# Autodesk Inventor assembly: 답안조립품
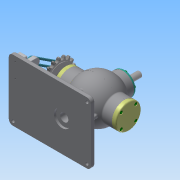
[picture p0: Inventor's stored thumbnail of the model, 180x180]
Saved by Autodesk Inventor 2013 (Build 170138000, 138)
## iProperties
Created: 2017-07
Part Number: 답안조립품
Document SubType Name: Assembly
Designer: Administrator
Author: Administrator
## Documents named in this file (20)
- C:\Users\Administrator\Desktop\370708V1026\답안조립품.iam
- C:\Users\Administrator\Desktop\370708V1026\본체.ipt
- C:\Users\Administrator\Desktop\370708V1026\고정핀.ipt
- C:\Users\Administrator\Desktop\370708V1026\너트 M8x1.ipt
- C:\Users\Administrator\Desktop\370708V1026\둥근머리 볼트 M4x8.ipt
- C:\Users\Administrator\Desktop\370708V1026\뒤커버.ipt
- C:\Users\Administrator\Desktop\370708V1026\베어링 6202.ipt
- C:\Users\Administrator\Desktop\370708V1026\본체커버.ipt
- C:\Users\Administrator\Desktop\370708V1026\볼트 M4x12.ipt
- C:\Users\Administrator\Desktop\370708V1026\스프로킷.ipt
- C:\Users\Administrator\Desktop\370708V1026\슬라이드 커버.ipt
- C:\Users\Administrator\Desktop\370708V1026\슬라이드.ipt
- C:\Users\Administrator\Desktop\370708V1026\앞커버.ipt
- C:\Users\Administrator\Desktop\370708V1026\연결대.ipt
- C:\Users\Administrator\Desktop\370708V1026\오일실.ipt
- C:\Users\Administrator\Desktop\370708V1026\와셔 8x17.ipt
- C:\Users\Administrator\Desktop\370708V1026\와셔 ISO 7093 A.ipt
- C:\Users\Administrator\Desktop\370708V1026\축.ipt
- C:\Users\Administrator\Desktop\370708V1026\키 3 x 3 x 12.ipt
- C:\Users\Administrator\Desktop\370708V1026\스프링.ipt
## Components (1 placed, 1 different names)
1. 고정핀:1
